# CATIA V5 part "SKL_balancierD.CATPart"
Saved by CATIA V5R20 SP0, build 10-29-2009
Part number: SKL_balancierD
Publications: "Axe_F_balancierD", "Axe_B_balancierD", "Plan_Ref", "Segement_BF", "F", "B", "Plan_Sec", "Plan_Ter"
Bounding box of the stored display mesh (mm): x -5 to 5, y 24 to 26.656, z 0 to 5.779
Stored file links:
  C:\Users\MATT\Desktop\CATIA_Projet_IAO\CATIA FINAL\SKL_balancierD.CATPart
  C:\Users\MATT\Desktop\CATIA_Projet_IAO\CATIA FINAL\SKL_Parametre_Projet_IAO.CATProduct
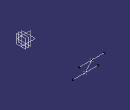
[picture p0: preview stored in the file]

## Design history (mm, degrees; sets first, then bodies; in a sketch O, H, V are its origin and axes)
External parameters (linked from other documents)
  External.AC = 3 mm
Set1
  Point1 "B": type OnCurve, Support Sketch1, RefPoint {extremum Reference Sketch1, Direction (1, 2, 3)}, Length 1
  Point2 "F": (0, 0, 0), relative to Point3
  Line1 "Segement_BF": type PtPt, FirstPoint Point1, SecondPoint Point2
  Plane1 "Plan_Ref": type Offset, RefPlane Plane4, Offset 0
  Line2 "Axe_B_balancierD": type Normal, RefPoint Point1, RefSkin Plane1, Start -5, End 5
  Line3 "Axe_F_balancierD": type Normal, RefPoint Point2, RefSkin Plane1, Start -5, End 5
  Sketch1 on Plane1, origin (0, 0, 0), H (0, 1, 0), V (0, 0, 1)
    circle A1 centre (24, 0) radius 6.36
    point P1 (24, 0)
    reference projected point E1 (24, 0) from Point2
    radius A1 = 6.36 {= 2.12*External.AC}
    coincidence: P1 E1
  Plane2 "Plan_Sec": type Offset, RefPlane Plane5, Offset 0
  Plane3 "Plan_Ter": type Offset, RefPlane Plane6, Offset 0
Set2
  Point3 "F": linked copy from another document
  Plane4 "Plan_Ref": linked copy from another document
  Plane5 "Plan_Sec": linked copy from another document
  Plane6 "Plan_Ter": linked copy from another document
Body1 (main body)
